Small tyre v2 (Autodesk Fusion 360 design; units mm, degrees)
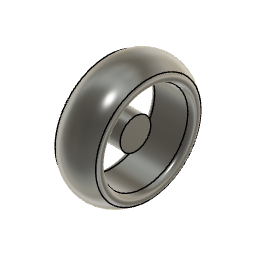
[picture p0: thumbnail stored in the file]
sketch "Sketch1" plane through (0, 0, 0) normal (1, 0, 0) x axis (0, 1, 0)
  circle C1 centre (24.9666, 12.7062) radius 12.6513
extrude "Extrude1" new body sketch "Sketch1" along normal blind 10
hole "Hole1" HoleDepth 10 HoleDiameter 10 TipAngle 118 CBDepth 1 CBDiameter 16
delete_face "DeleteFace1"
fillet "Fillet1" radius 5.5
fillet "Fillet2" radius 1
fillet "Fillet3" radius 1
sketch "Sketch2" plane through (0, 0, 0) normal (1, 0, 0) x axis (0, 1, 0)
  circle C1 centre (25, 13) radius 2.8284
extrude "Extrude2" new body sketch "Sketch2" along normal blind 5
sketch "Sketch3" plane through (0, 0, 0) normal (1, 0, 0) x axis (0, 1, 0)
sketch "Sketch4" plane through (0, 0, 0) normal (1, 0, 0) x axis (0, 1, 0)
move_face "MoveFace1"
move_face "MoveFace2"
move_face "MoveFace3"
move_face "MoveFace4"
move_face "MoveFace5"
move_face "MoveFace6"
fillet "Fillet4" radius 5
